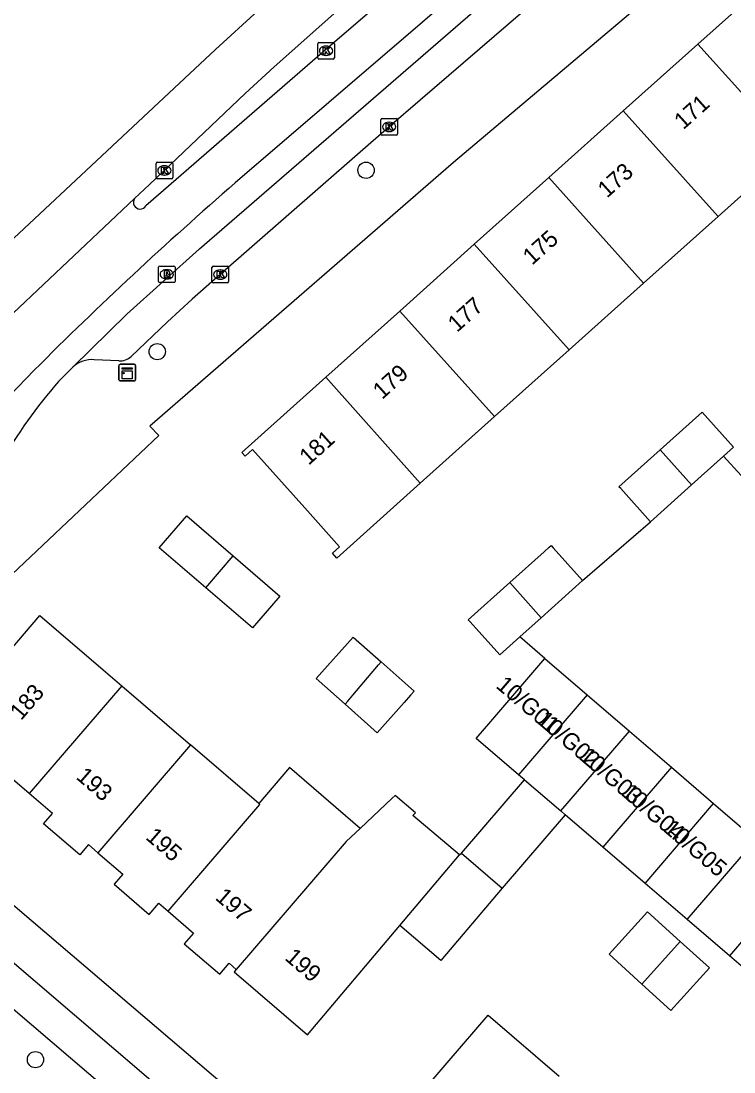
# Model space of a CAD drawing. Extents: x 162532 to 163264, y 381233 to 382042.
# Drawn here: x 162555.3 to 162598.2, y 381794.9 to 381858.1 of the extents above; entities that cross this region are included whole.
import ezdxf

# ---------------------------------------------------------------- set-up
doc = ezdxf.new("R2010")
doc.units = 0
for name, color, linetype in [('IMGEO_Boom', 7, 'Continuous'), ('IMGEO_Fietspad_gesloten', 7, 'Continuous'), ('IMGEO_Kast', 7, 'Continuous'), ('IMGEO_Kolk', 7, 'Continuous'), ('IMGEO_Pand', 7, 'Continuous'), ('IMGEO_Pand_nummerreeks', 7, 'Continuous'), ('IMGEO_Rijbaan_lokaal_open', 7, 'Continuous'), ('IMGEO_Rijbaan_regionaal_gesloten', 7, 'Continuous'), ('IMGEO_Rioolput', 7, 'Continuous'), ('IMGEO_Voetpad_open', 7, 'Continuous')]:
    doc.layers.add(name, color=color, linetype=linetype)

msp = doc.modelspace()

# ---------------------------------------------------------------- linework, layer by layer
at = {"layer": 'IMGEO_Boom'}
for centre in [(162576.058, 381849.122), (162563.506, 381838.213), (162556.188, 381795.627)]:
    msp.add_circle(centre, 0.489, dxfattribs=at)
at = {"layer": 'IMGEO_Fietspad_gesloten'}
for points in [[(162558.429, 381837.287), (162561.681, 381840.461), (162566.047, 381844.39), (162586.056, 381861.754), (162592.049, 381866.695)], [(162558.429, 381837.287), (162558.305, 381837.166), (162557.574, 381836.413)], [(162680.601, 381693.932), (162634.563, 381733.29), (162601.096, 381761.857), (162549.056, 381806.402), (162548.287, 381807.068)], [(162546.004, 381806.321), (162547.12, 381805.283), (162565.997, 381789.141)]]:
    msp.add_lwpolyline(points, dxfattribs=at)
msp.add_arc((162579.088, 381817.51), 28.639, 138.69514, 150.74787, dxfattribs=at)
at = {"layer": 'IMGEO_Kast'}
for p, q in [((162561.203, 381836.527), (162561.203, 381837.368)), ((162561.203, 381837.368), (162561.203, 381836.527)), ((162561.278, 381837.452), (162562.119, 381837.452)), ((162562.119, 381837.452), (162561.278, 381837.452)), ((162562.203, 381837.377), (162562.203, 381836.536)), ((162562.203, 381836.536), (162562.203, 381837.377)), ((162562.128, 381836.452), (162561.287, 381836.452)), ((162561.287, 381836.452), (162562.128, 381836.452))]:
    msp.add_line(p, q, dxfattribs=at)
for points in [[(162561.398, 381837.242), (162561.998, 381837.242), (162561.998, 381837.157), (162561.398, 381837.157), (162561.398, 381837.242)], [(162561.398, 381837.067), (162561.998, 381837.067), (162561.998, 381836.578), (162561.398, 381836.578), (162561.398, 381837.067)]]:
    msp.add_lwpolyline(points, dxfattribs=at)
msp.add_circle((162561.482, 381836.916), 0.0377, dxfattribs=at)
for centre, start, end in [((162561.281, 381837.374), 92.4484, 184.28452), ((162561.281, 381837.374), 92.4484, 184.28452), ((162562.125, 381837.374), 2.4484, 94.28452), ((162562.125, 381837.374), 2.4484, 94.28452), ((162561.281, 381836.53), 182.4484, 274.28452), ((162561.281, 381836.53), 182.4484, 274.28452), ((162562.125, 381836.53), 272.4484, 4.28452), ((162562.125, 381836.53), 272.4484, 4.28452)]:
    msp.add_arc(centre, 0.0779, start, end, dxfattribs=at)
at = {"layer": 'IMGEO_Kolk'}
for p, q in [((162573.15, 381855.883), (162573.15, 381856.735)), ((162573.225, 381856.809), (162574.077, 381856.809)), ((162574.151, 381856.735), (162574.151, 381855.883)), ((162573.638, 381856.589), (162573.663, 381856.589)), ((162574.077, 381855.809), (162573.225, 381855.809)), ((162573.661, 381856.029), (162573.636, 381856.029)), ((162576.947, 381851.305), (162576.947, 381852.157)), ((162577.022, 381852.231), (162577.874, 381852.231)), ((162577.435, 381852.011), (162577.46, 381852.011)), ((162577.948, 381852.157), (162577.948, 381851.305)), ((162577.874, 381851.231), (162577.022, 381851.231)), ((162577.458, 381851.451), (162577.433, 381851.451)), ((162563.436, 381848.686), (162563.436, 381849.538)), ((162563.511, 381849.612), (162564.363, 381849.612)), ((162563.924, 381849.392), (162563.949, 381849.392)), ((162564.437, 381849.538), (162564.437, 381848.686)), ((162564.363, 381848.612), (162563.511, 381848.612)), ((162563.947, 381848.832), (162563.922, 381848.832)), ((162566.795, 381842.424), (162566.795, 381843.276)), ((162566.87, 381843.35), (162567.722, 381843.35)), ((162567.283, 381843.13), (162567.308, 381843.13)), ((162567.796, 381843.276), (162567.796, 381842.424)), ((162567.722, 381842.35), (162566.87, 381842.35)), ((162567.306, 381842.57), (162567.281, 381842.57))]:
    msp.add_line(p, q, dxfattribs=at)
for points in [[(162573.15, 381855.883), (162573.15, 381856.735)], [(162573.225, 381856.809), (162574.077, 381856.809)], [(162574.151, 381856.735), (162574.151, 381855.883)], [(162573.471, 381856.509), (162573.594, 381856.509), (162573.594, 381856.358), (162573.724, 381856.509), (162573.888, 381856.509), (162573.742, 381856.358), (162573.895, 381856.109), (162573.743, 381856.109), (162573.658, 381856.273), (162573.594, 381856.206), (162573.594, 381856.109), (162573.471, 381856.109), (162573.471, 381856.509)], [(162574.077, 381855.809), (162573.225, 381855.809)], [(162576.947, 381851.305), (162576.947, 381852.157)], [(162577.022, 381852.231), (162577.874, 381852.231)], [(162577.268, 381851.931), (162577.391, 381851.931), (162577.391, 381851.78), (162577.521, 381851.931), (162577.685, 381851.931), (162577.539, 381851.78), (162577.692, 381851.531), (162577.54, 381851.531), (162577.455, 381851.695), (162577.391, 381851.628), (162577.391, 381851.531), (162577.268, 381851.531), (162577.268, 381851.931)], [(162577.948, 381852.157), (162577.948, 381851.305)], [(162577.874, 381851.231), (162577.022, 381851.231)], [(162563.436, 381848.686), (162563.436, 381849.538)], [(162563.511, 381849.612), (162564.363, 381849.612)], [(162563.757, 381849.312), (162563.88, 381849.312), (162563.88, 381849.161), (162564.01, 381849.312), (162564.174, 381849.312), (162564.028, 381849.161), (162564.181, 381848.912), (162564.029, 381848.912), (162563.944, 381849.076), (162563.88, 381849.009), (162563.88, 381848.912), (162563.757, 381848.912), (162563.757, 381849.312)], [(162564.437, 381849.538), (162564.437, 381848.686)], [(162564.363, 381848.612), (162563.511, 381848.612)], [(162566.795, 381842.424), (162566.795, 381843.276)], [(162566.87, 381843.35), (162567.722, 381843.35)], [(162567.116, 381843.05), (162567.239, 381843.05), (162567.239, 381842.899), (162567.369, 381843.05), (162567.533, 381843.05), (162567.387, 381842.899), (162567.54, 381842.65), (162567.388, 381842.65), (162567.303, 381842.814), (162567.239, 381842.747), (162567.239, 381842.65), (162567.116, 381842.65), (162567.116, 381843.05)], [(162567.796, 381843.276), (162567.796, 381842.424)], [(162567.722, 381842.35), (162566.87, 381842.35)]]:
    msp.add_lwpolyline(points, dxfattribs=at)
for centre, start, end in [((162573.227, 381856.733), 91.55205, 178.44795), ((162573.227, 381856.733), 91.55205, 178.44795), ((162574.075, 381856.733), 1.55205, 88.44795), ((162574.075, 381856.733), 1.55205, 88.44795), ((162573.227, 381855.885), 181.55205, 268.44795), ((162573.227, 381855.885), 181.55205, 268.44795), ((162574.075, 381855.885), 271.55205, 358.44795), ((162574.075, 381855.885), 271.55205, 358.44795), ((162577.024, 381852.155), 91.55205, 178.44795), ((162577.024, 381852.155), 91.55205, 178.44795), ((162577.872, 381852.155), 1.55205, 88.44795), ((162577.872, 381852.155), 1.55205, 88.44795), ((162577.024, 381851.307), 181.55205, 268.44795), ((162577.024, 381851.307), 181.55205, 268.44795), ((162577.872, 381851.307), 271.55205, 358.44795), ((162577.872, 381851.307), 271.55205, 358.44795), ((162563.513, 381849.536), 91.55205, 178.44795), ((162563.513, 381849.536), 91.55205, 178.44795), ((162564.361, 381849.536), 1.55205, 88.44795), ((162564.361, 381849.536), 1.55205, 88.44795), ((162563.513, 381848.688), 181.55205, 268.44795), ((162563.513, 381848.688), 181.55205, 268.44795), ((162564.361, 381848.688), 271.55205, 358.44795), ((162564.361, 381848.688), 271.55205, 358.44795), ((162566.872, 381843.274), 91.55205, 178.44795), ((162566.872, 381843.274), 91.55205, 178.44795), ((162567.72, 381843.274), 1.55205, 88.44795), ((162567.72, 381843.274), 1.55205, 88.44795), ((162566.872, 381842.426), 181.55205, 268.44795), ((162566.872, 381842.426), 181.55205, 268.44795), ((162567.72, 381842.426), 271.55205, 358.44795), ((162567.72, 381842.426), 271.55205, 358.44795)]:
    msp.add_arc(centre, 0.0765, start, end, dxfattribs=at)
for centre, major_axis, ratio, start_param, end_param in [((162573.637, 381856.309), (-0.387, 0.002), 0.722429, 4.712389, 7.853982), ((162573.662, 381856.309), (-0.39, 0.002), 0.717154, 1.570796, 4.712389), ((162577.434, 381851.731), (-0.387, 0.002), 0.722429, 4.712389, 7.853982), ((162577.459, 381851.731), (-0.39, 0.002), 0.717154, 1.570796, 4.712389), ((162563.923, 381849.112), (-0.387, 0.002), 0.722429, 4.712389, 7.853982), ((162563.948, 381849.112), (-0.39, 0.002), 0.717154, 1.570796, 4.712389), ((162567.282, 381842.85), (-0.387, 0.002), 0.722429, 4.712389, 7.853982), ((162567.307, 381842.85), (-0.39, 0.002), 0.717154, 1.570796, 4.712389)]:
    msp.add_ellipse(centre, major_axis=major_axis, ratio=ratio, start_param=start_param, end_param=end_param, dxfattribs=at)
at = {"layer": 'IMGEO_Pand'}
for points in [[(162596.004, 381856.717), (162600.585, 381860.822)], [(162591.518, 381852.697), (162596.004, 381856.717)], [(162596.004, 381856.717), (162601.7, 381850.363)], [(162587.041, 381848.684), (162591.518, 381852.697)], [(162591.518, 381852.697), (162597.214, 381846.343)], [(162601.7, 381850.363), (162597.214, 381846.343)], [(162582.563, 381844.671), (162587.041, 381848.684)], [(162587.041, 381848.684), (162592.736, 381842.329)], [(162597.214, 381846.343), (162592.736, 381842.329)], [(162578.085, 381840.657), (162582.563, 381844.671)], [(162588.257, 381838.316), (162582.563, 381844.671)], [(162592.736, 381842.329), (162588.257, 381838.316)], [(162573.641, 381836.675), (162578.085, 381840.657)], [(162578.085, 381840.657), (162583.779, 381834.303)], [(162588.257, 381838.316), (162583.779, 381834.303)], [(162579.309, 381830.297), (162574.292, 381825.801), (162574.034, 381826.09), (162574.468, 381826.479), (162572.369, 381828.821), (162569.236, 381832.318), (162568.797, 381831.925), (162568.594, 381832.152), (162573.641, 381836.675)], [(162579.309, 381830.297), (162573.641, 381836.675)], [(162583.779, 381834.303), (162579.309, 381830.297)], [(162593.737, 381832.31), (162596.262, 381834.573), (162598.149, 381832.467), (162597.546, 381831.927)], [(162593.148, 381827.986), (162591.362, 381829.978), (162591.26, 381830.091), (162593.737, 381832.31)], [(162595.624, 381830.205), (162593.737, 381832.31)], [(162597.546, 381831.927), (162595.624, 381830.205)], [(162595.624, 381830.205), (162593.148, 381827.986)], [(162566.419, 381824.016), (162563.631, 381826.412), (162565.279, 381828.33), (162568.062, 381825.938)], [(162584.7, 381824.334), (162586.76, 381826.18), (162587.055, 381826.444), (162587.178, 381826.554), (162587.297, 381826.422), (162589.074, 381824.44)], [(162568.062, 381825.938), (162570.883, 381823.515), (162569.234, 381821.597), (162566.419, 381824.016)], [(162566.419, 381824.016), (162568.062, 381825.938)], [(162585.305, 381821.062), (162584.09, 381819.973), (162582.313, 381821.956), (162582.194, 381822.089), (162584.7, 381824.334)], [(162584.7, 381824.334), (162586.584, 381822.209)], [(162586.584, 381822.209), (162589.074, 381824.44)], [(162555.802, 381811.633), (162550.14, 381816.499), (162552.796, 381819.59), (162553.542, 381818.95), (162556.455, 381822.339), (162560.247, 381819.08), (162561.371, 381818.114)], [(162586.584, 381822.209), (162585.305, 381821.062)], [(162574.802, 381817.007), (162573.065, 381818.549), (162575.284, 381821.048), (162576.968, 381819.554)], [(162576.968, 381819.554), (162578.95, 381817.795), (162578.733, 381817.551), (162578.339, 381817.108), (162576.73, 381815.295), (162574.802, 381817.007)], [(162574.802, 381817.007), (162574.964, 381817.198), (162575.272, 381817.56), (162576.811, 381819.37), (162576.968, 381819.554)], [(162585.219, 381812.769), (162582.685, 381814.947), (162583.554, 381815.958), (162586.812, 381819.75)], [(162586.812, 381819.75), (162589.347, 381817.572)], [(162561.371, 381818.114), (162555.802, 381811.633)], [(162561.371, 381818.114), (162565.507, 381814.56)], [(162589.347, 381817.572), (162585.219, 381812.769)], [(162589.347, 381817.572), (162591.882, 381815.394)], [(162587.755, 381810.591), (162591.882, 381815.394)], [(162591.882, 381815.394), (162594.416, 381813.215)], [(162565.507, 381814.56), (162559.94, 381808.078)], [(162569.606, 381811.039), (162565.507, 381814.56)], [(162575.706, 381809.539), (162571.456, 381813.192), (162569.606, 381811.039)], [(162594.416, 381813.215), (162590.289, 381808.413)], [(162594.416, 381813.215), (162596.951, 381811.037)], [(162585.58, 381812.459), (162585.219, 381812.769)], [(162581.787, 381808.045), (162585.58, 381812.459)], [(162585.58, 381812.459), (162587.755, 381810.591)], [(162559.94, 381808.078), (162559.378, 381808.561), (162558.846, 381807.942), (162556.676, 381809.806), (162557.208, 381810.425), (162555.802, 381811.633)], [(162581.666, 381807.939), (162578.861, 381810.308), (162579.039, 381810.476), (162577.801, 381811.522), (162577.623, 381811.353), (162575.706, 381809.539)], [(162564.155, 381804.552), (162569.675, 381810.979), (162569.606, 381811.039)], [(162587.755, 381810.591), (162588.022, 381810.361)], [(162592.824, 381806.234), (162596.951, 381811.037)], [(162596.951, 381811.037), (162599.486, 381808.859)], [(162588.022, 381810.361), (162584.229, 381805.946)], [(162590.289, 381808.413), (162588.022, 381810.361)], [(162575.706, 381809.539), (162574.87, 381808.749), (162568.257, 381801.059)], [(162595.359, 381804.056), (162599.486, 381808.859)], [(162559.94, 381808.078), (162561.434, 381806.794), (162560.907, 381806.181), (162563.021, 381804.364), (162563.596, 381805.033), (162564.155, 381804.552)], [(162592.824, 381806.234), (162590.289, 381808.413)], [(162578.078, 381803.689), (162581.666, 381807.939)], [(162581.666, 381807.939), (162581.787, 381808.045)], [(162581.787, 381808.045), (162584.229, 381805.946)], [(162595.359, 381804.056), (162592.824, 381806.234)], [(162602.021, 381806.68), (162597.894, 381801.878)], [(162584.229, 381805.946), (162580.559, 381801.594), (162578.078, 381803.689)], [(162564.155, 381804.552), (162565.683, 381803.24), (162565.134, 381802.602), (162567.261, 381800.773), (162567.826, 381801.43), (162568.257, 381801.059)], [(162592.637, 381800.174), (162590.661, 381801.967), (162592.98, 381804.522), (162594.94, 381802.744)], [(162568.257, 381801.059), (162568.124, 381800.904), (162572.53, 381797.118), (162578.078, 381803.689)], [(162597.894, 381801.878), (162595.359, 381804.056)], [(162594.94, 381802.744), (162596.703, 381801.144), (162594.384, 381798.589), (162592.637, 381800.174)], [(162594.94, 381802.744), (162592.637, 381800.174)], [(162600.429, 381799.7), (162597.894, 381801.878)], [(162582.105, 381788.159), (162580.674, 381789.389), (162580.064, 381788.68), (162578.025, 381790.432), (162578.596, 381791.097), (162577.8, 381791.781), (162581.059, 381795.574), (162583.406, 381798.306), (162587.674, 381794.638)]]:
    msp.add_lwpolyline(points, dxfattribs=at)
at = {"layer": 'IMGEO_Rijbaan_lokaal_open'}
for points in [[(162589.487, 381869.827), (162588.508, 381868.991), (162582.504, 381864.006), (162573.602, 381856.338), (162562.824, 381846.988)], [(162591.078, 381867.896), (162585.082, 381862.888), (162568.19, 381848.358)], [(162556.114, 381837.102), (162554.652, 381835.58)], [(162597.546, 381831.927), (162598.608, 381830.759)], [(162589.074, 381824.44), (162593.148, 381827.986)], [(162586.812, 381819.75), (162585.305, 381821.062)]]:
    msp.add_lwpolyline(points, dxfattribs=at)
for centre, radius, start, end in [((162722.245, 381670.975), 234.942, 130.97379, 135.00056), ((162562.479, 381847.193), 0.401, 145.9956, 329.28133)]:
    msp.add_arc(centre, radius, start, end, dxfattribs=at)
at = {"layer": 'IMGEO_Rijbaan_regionaal_gesloten'}
for points in [[(162536.507, 381827.181), (162540.157, 381830.785), (162552.383, 381842.71), (162567.001, 381856.379), (162572.096, 381861.048), (162587.252, 381874.266), (162599.477, 381884.467), (162624.285, 381904.911), (162662.123, 381935.842), (162667.509, 381940.274), (162683.823, 381953.589), (162710.356, 381975.317), (162716.011, 381979.972), (162720.796, 381983.875), (162725.296, 381987.518), (162732.266, 381992.774), (162738.678, 381997.54), (162745.062, 382002.248), (162751.538, 382007.048), (162758.019, 382011.857), (162764.398, 382016.604), (162770.791, 382021.331), (162777.282, 382026.141), (162780.539, 382028.529)], [(162562.147, 381847.417), (162563.048, 381848.267), (162568.79, 381853.73), (162570.541, 381855.349), (162576.654, 381860.802), (162581.631, 381865.192), (162587.814, 381870.584), (162593.659, 381875.675), (162600.282, 381881.209), (162616.901, 381894.769), (162628.275, 381903.978), (162646.842, 381919.202), (162662.907, 381932.358), (162665.643, 381934.608), (162671.529, 381939.448), (162680.739, 381946.928), (162688.64, 381953.42), (162696.581, 381959.932), (162705.643, 381967.393), (162712.504, 381972.937), (162718.866, 381978.131), (162722.177, 381980.799), (162726.008, 381983.557)], [(162562.147, 381847.417), (162551.188, 381837.076), (162542.033, 381827.792)]]:
    msp.add_lwpolyline(points, dxfattribs=at)
at = {"layer": 'IMGEO_Rioolput'}
for p, q in [((162563.577, 381842.438), (162563.577, 381843.29)), ((162563.652, 381843.364), (162564.504, 381843.364)), ((162564.065, 381843.144), (162564.09, 381843.144)), ((162564.578, 381843.29), (162564.578, 381842.438)), ((162564.504, 381842.364), (162563.652, 381842.364)), ((162564.088, 381842.584), (162564.063, 381842.584))]:
    msp.add_line(p, q, dxfattribs=at)
for points in [[(162563.577, 381842.438), (162563.577, 381843.29)], [(162563.652, 381843.364), (162564.504, 381843.364)], [(162564.166, 381843.062), (162563.914, 381843.064), (162563.914, 381842.664)], [(162563.914, 381842.664), (162564.038, 381842.664), (162564.038, 381842.826), (162564.049, 381842.826)], [(162564.092, 381842.983), (162564.038, 381842.983), (162564.038, 381842.902)], [(162564.038, 381842.902), (162564.09, 381842.902)], [(162564.578, 381843.29), (162564.578, 381842.438)], [(162564.504, 381842.364), (162563.652, 381842.364)], [(162564.096, 381842.797), (162564.167, 381842.664), (162564.307, 381842.664), (162564.242, 381842.79)]]:
    msp.add_lwpolyline(points, dxfattribs=at)
for centre, radius, start, end in [((162563.654, 381843.288), 0.0765, 91.55205, 178.44795), ((162563.654, 381843.288), 0.0765, 91.55205, 178.44795), ((162564.048, 381842.773), 0.0533, 26.02933, 88.69889), ((162564.074, 381843.091), 0.19, 274.7715, 282.96867), ((162564.098, 381842.887), 0.0964, 77.00612, 93.18647), ((162564.112, 381842.944), 0.0378, 276.66336, 79.67722), ((162564.165, 381842.952), 0.109, 350.36119, 89.41601), ((162564.163, 381842.952), 0.112, 277.58423, 350.98172), ((162564.147, 381842.737), 0.108, 29.51342, 73.79051), ((162564.502, 381843.288), 0.0765, 1.55205, 88.44795), ((162564.502, 381843.288), 0.0765, 1.55205, 88.44795), ((162563.654, 381842.44), 0.0765, 181.55205, 268.44795), ((162563.654, 381842.44), 0.0765, 181.55205, 268.44795), ((162564.502, 381842.44), 0.0765, 271.55205, 358.44795), ((162564.502, 381842.44), 0.0765, 271.55205, 358.44795)]:
    msp.add_arc(centre, radius, start, end, dxfattribs=at)
for centre, major_axis, ratio, start_param, end_param in [((162564.064, 381842.864), (-0.387, 0.002), 0.722429, 4.712389, 7.853982), ((162564.089, 381842.864), (-0.39, 0.002), 0.717154, 1.570796, 4.712389)]:
    msp.add_ellipse(centre, major_axis=major_axis, ratio=ratio, start_param=start_param, end_param=end_param, dxfattribs=at)
at = {"layer": 'IMGEO_Voetpad_open'}
for points in [[(162593.31, 381865.148), (162592.352, 381864.452), (162586.484, 381859.535), (162577.447, 381851.731), (162567.295, 381842.85), (162565.606, 381841.378), (162564.129, 381840.002), (162561.944, 381837.921)], [(162597.983, 381863.68), (162581.307, 381849.596), (162563.057, 381833.73), (162563.598, 381833.161), (162548.153, 381818.57)], [(162561.195, 381837.654), (162559.72, 381837.729)], [(162549.054, 381809.864), (162602.511, 381764.218)]]:
    msp.add_lwpolyline(points, dxfattribs=at)
for centre, radius, start, end in [((162561.237, 381838.72), 1.067, 267.73913, 311.50066), ((162559.605, 381835.959), 1.774, 86.27939, 131.51996)]:
    msp.add_arc(centre, radius, start, end, dxfattribs=at)

# ---------------------------------------------------------------- texts
at = {"layer": 'IMGEO_Pand_nummerreeks'}
for s, rotation, p in [('171', 41.86673, (162595.129, 381851.528)), ('173', 41.86673, (162590.539, 381847.414)), ('175', 41.86673, (162586.033, 381843.376)), ('177', 41.86673, (162581.527, 381839.338)), ('179', 41.86673, (162577.022, 381835.3)), ('181', 41.86673, (162572.601, 381831.338)), ('183', 49.31944, (162555.318, 381815.985)), ('10/G01', 319.39871, (162583.809, 381818.043)), ('10/G02', 319.39871, (162586.258, 381815.944)), ('10/G03', 319.39871, (162588.8, 381813.766)), ('193', 319.05107, (162558.572, 381812.566)), ('10/G04', 319.39871, (162591.337, 381811.591)), ('10/G05', 319.39871, (162593.874, 381809.416)), ('195', 319.05071, (162562.754, 381808.937)), ('197', 319.05071, (162566.936, 381805.308)), ('199', 319.05071, (162571.118, 381801.68))]:
    msp.add_text(s, height=1, rotation=rotation, dxfattribs=at).set_placement(p)

doc.saveas('drawing.dxf')
